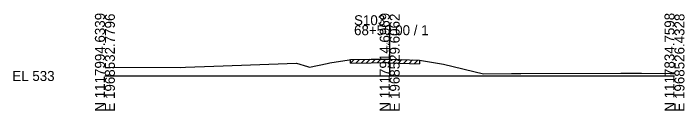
# Model space of a CAD drawing. Extents: x -26 to 163, y -10 to 45020.
# Drawn here: x -25.7 to 162.8, y 27490.3 to 27517.5 of the extents above; entities that cross this region are included whole.
import ezdxf

# ---------------------------------------------------------------- set-up
doc = ezdxf.new("R2010")
doc.units = 0
for name, color, linetype in [('RD_GPK_XS_Cell', 7, 'Continuous'), ('RD_XS_ExGround', 7, 'Continuous'), ('RD_XS_ExPaveRet', 7, 'Continuous'), ('RD_XS_TX_Elev_EX', 7, 'Continuous')]:
    doc.layers.add(name, color=color, linetype=linetype)

msp = doc.modelspace()

# ---------------------------------------------------------------- linework, layer by layer
at = {"layer": 'RD_GPK_XS_Cell'}
for p, q in [((80, 27500), (80, 27514.23)), ((0, 27500), (80, 27500)), ((80, 27500), (160, 27500))]:
    msp.add_line(p, q, dxfattribs=at)
at = {"layer": 'RD_XS_ExGround'}
for p, q in [((30.6, 27502.76), (53.84, 27503.63)), ((53.84, 27503.63), (56.94, 27502.63)), ((57.45, 27502.48), (62.41, 27503.54)), ((62.41, 27503.54), (63.23, 27503.71)), ((63.23, 27503.71), (68.62, 27504.53)), ((68.62, 27504.53), (68.97, 27504.58)), ((68.97, 27504.58), (74.8, 27504.68)), ((74.8, 27504.68), (78.41, 27504.74)), ((78.41, 27504.74), (80, 27504.69)), ((80, 27504.69), (88.37, 27504.41)), ((88.37, 27504.41), (95.11, 27503.32)), ((95.11, 27503.32), (106.36, 27500.64)), ((0, 27502.45), (21.11, 27502.4)), ((21.11, 27502.4), (22.61, 27502.46)), ((22.61, 27502.46), (30.6, 27502.76)), ((56.94, 27502.63), (57.45, 27502.48)), ((106.36, 27500.64), (114.19, 27500.7)), ((114.19, 27500.7), (116.83, 27500.7)), ((116.83, 27500.7), (144.92, 27500.79)), ((144.92, 27500.79), (150.74, 27500.78)), ((150.74, 27500.78), (158.78, 27500.7)), ((158.78, 27500.7), (160, 27500.69))]:
    msp.add_line(p, q, dxfattribs=at)
at = {"layer": 'RD_XS_ExPaveRet'}
for p, q in [((68.97, 27503.58), (69.99, 27504.6)), ((68.97, 27503.58), (68.97, 27504.58)), ((68.97, 27503.58), (74.8, 27503.68)), ((70.47, 27503.61), (71.49, 27504.62)), ((71.97, 27503.63), (72.99, 27504.65)), ((73.47, 27503.66), (74.49, 27504.67)), ((74.8, 27503.68), (78.41, 27503.74)), ((74.97, 27503.68), (75.99, 27504.7)), ((76.47, 27503.71), (77.49, 27504.73)), ((77.97, 27503.74), (78.96, 27504.72)), ((78.41, 27503.74), (80, 27503.69)), ((79.47, 27503.71), (80.44, 27504.68)), ((80, 27503.69), (88.37, 27503.41)), ((80.97, 27503.66), (81.94, 27504.63)), ((82.47, 27503.61), (83.44, 27504.58)), ((83.97, 27503.56), (84.94, 27504.53)), ((85.47, 27503.51), (86.44, 27504.48)), ((86.97, 27503.46), (87.94, 27504.43)), ((88.37, 27504.41), (88.37, 27503.41))]:
    msp.add_line(p, q, dxfattribs=at)

# ---------------------------------------------------------------- texts
at = {"layer": 'RD_GPK_XS_Cell'}
for s, p in [('N 1117994.6339', (0, 27490)), ('E 1968532.7796', (2.8, 27490)), ('N 1117914.6969', (80, 27490)), ('E 1968529.6062', (82.8, 27490)), ('N 1117834.7598', (160, 27490)), ('E 1968526.4328', (162.8, 27490))]:
    msp.add_text(s, height=2.8, rotation=90, dxfattribs=at).set_placement(p)
for s, p in [('S103', (70, 27514.23)), ('68+50.00 / 1', (70, 27511.43)), ('EL 533', (-26, 27498.6))]:
    msp.add_text(s, height=2.8, dxfattribs=at).set_placement(p)
at = {"layer": 'RD_XS_TX_Elev_EX'}
msp.add_text('537.69', height=0.8, rotation=90, dxfattribs=at).set_placement((79.9, 27506.69))

doc.saveas('drawing.dxf')
